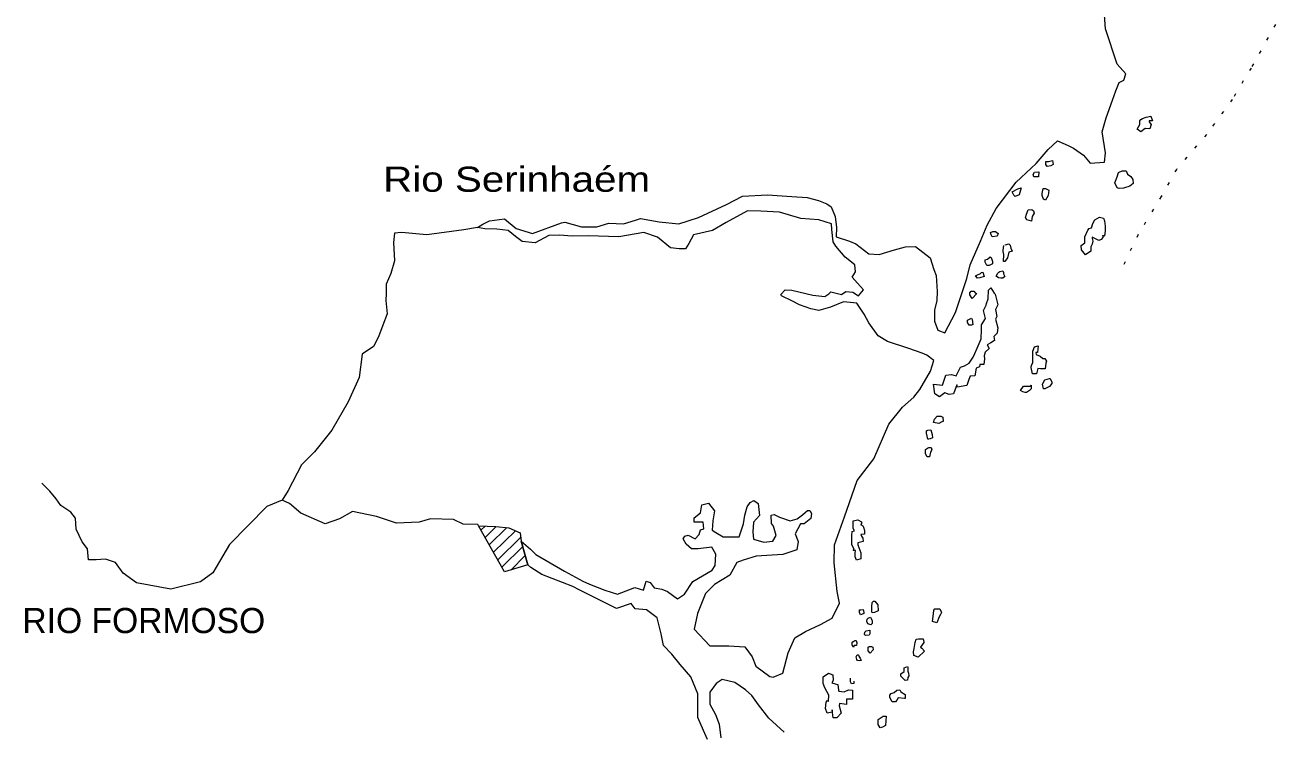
# Model space of a CAD drawing. Extents: x 47169 to 972804, y 7447977 to 9608469.
# Drawn here: x 910159 to 944005, y 9035587 to 9054600 of the extents above; entities that cross this region are included whole.
import ezdxf
from ezdxf.enums import TextEntityAlignment as Align

# ---------------------------------------------------------------- set-up
doc = ezdxf.new("R2010")
doc.units = 0
doc.header["$LTSCALE"] = 270
doc.linetypes.add('DOTTED', pattern=[1.5, 0.3, -1.2])
doc.layers.add('1', color=7, linetype='Continuous', lineweight=13)
doc.layers.add('3', color=7, linetype='Continuous')

msp = doc.modelspace()

# ---------------------------------------------------------------- linework, layer by layer
at = {"layer": '1'}
for p, q in [((922423.9, 9041014.5), (922536.4, 9041125.3)), ((922536.6, 9040816.1), (922837.3, 9041111.2)), ((922650.4, 9040616.6), (923122.6, 9041082.8)), ((922763.1, 9040418.3), (923351.1, 9040996.3)), ((922876.8, 9040218.8), (923493.9, 9040827.5)), ((922989.5, 9040020.4), (923548.6, 9040571)), ((923224.7, 9039941.6), (923616.7, 9040327.6)), ((923675.9, 9040075.5), (923684.8, 9040085.4))]:
    msp.add_line(p, q, dxfattribs=at)
at = {"layer": '1', "linetype": 'DOTTED'}
msp.add_lwpolyline([(944005.3, 9054971), (943148.7, 9053447.1), (942644.5, 9052604.6), (941948.4, 9051658.7), (941141, 9050720.6), (940731.9, 9049991.2), (940107.8, 9048964.8), (939666.9, 9048042.9)], dxfattribs=at)
at = {"layer": '1'}
for points in [[(938224.3, 9051360.5), (938367, 9051287), (938636.4, 9051099.1), (938818.4, 9050888.9), (939201.5, 9050917), (939228.3, 9051165), (939146, 9051734.4), (939253.6, 9052109), (939418.4, 9052579.4), (939508.2, 9052834.5), (939598.8, 9053057.4), (939727.4, 9053120.3), (939784.3, 9053287.1), (939547.6, 9053546.7), (939229.8, 9054502), (939209.4, 9054871.2)], [(930608.6, 9047475.9), (930791.6, 9047474), (931357.1, 9047331.9), (931676.6, 9047296.5), (931788.8, 9047375.2), (931837.8, 9047422.3), (932123.9, 9047355.1), (932244.9, 9047433.7), (932435.6, 9047416.2), (932586.8, 9047318.2), (932716.3, 9047476.5), (932558.2, 9047654.3), (932416.6, 9047824.2), (932505.2, 9047967.3), (932482.8, 9048151.5), (932222.5, 9048362.5), (931977.3, 9048653.2), (931906.8, 9048774.7), (931870.5, 9049103.1), (931855.5, 9049255.1), (931513.5, 9049362.7), (931035.2, 9049400.8), (930461.1, 9049567.4), (929958.5, 9049596.9), (929600, 9049600.5), (929022.3, 9049295), (928660.5, 9049074.8), (928148.6, 9048960.4), (928018.3, 9048730.1), (927928.6, 9048579.2), (927760.9, 9048580.9), (927521.9, 9048607.7), (927174.1, 9048899.3), (926808.1, 9049023.8), (926136.2, 9048903.2), (925857.3, 9048913.7), (925322.5, 9048928), (924882.4, 9048924.7), (924539.7, 9048952.5), (924252.8, 9048939.9), (923883.6, 9048744.1), (923532.1, 9048779.8), (923358.1, 9048917.8), (923160, 9049071.6), (922849.5, 9049115.7), (922529.7, 9049118.9), (922330.4, 9049153.1), (922475.8, 9049248), (922652, 9049333.8), (923059.5, 9049385.1), (923375.7, 9049133.7), (923814.4, 9048993), (924591.5, 9049280), (924686.6, 9049303.4), (925133.1, 9049170.4), (925540.1, 9049174), (925868.7, 9049273.8), (926258.9, 9049253.2), (926587.5, 9049354), (926715.9, 9049400.4), (927217.9, 9049306.7), (927752.3, 9049253.6), (928280.2, 9049423.3), (929034.8, 9049774.7), (929459.6, 9050002), (930139.4, 9050035), (930793, 9049987.3), (931199.8, 9049966.6), (931510, 9049883.6), (931733, 9049792.7), (931852.4, 9049711.7), (931953.5, 9049454.6), (931990.1, 9049157.3), (931987.6, 9048909.1), (932345.9, 9048785.7), (932512.9, 9048719.7), (932862, 9048451.3), (933140.9, 9048431.8), (933556.9, 9048556.1), (933853.4, 9048640.6), (934117, 9048645.6), (934513.2, 9048344.6), (934613.6, 9048023.2), (934675.9, 9047863), (934703.6, 9047438.3), (934693.3, 9047190.2), (934634.4, 9046934.8), (934631.3, 9046638.9), (934717, 9046389.8), (934908.2, 9046323.5), (935193, 9046872.5), (935498, 9047781.4), (935588.9, 9048148.4), (935866.8, 9048786.1), (936046.7, 9049216.4), (936290.7, 9049669.4), (936833, 9050375.2), (937364.3, 9050874), (937688.2, 9051254.1), (937937.7, 9051492), (938224.3, 9051360.5)], [(937700.3, 9050933.7), (937804.2, 9050957), (937827.4, 9050852.6), (937763, 9050813.4), (937666.9, 9050797.7), (937627.7, 9050846.9), (937628.3, 9050902.3), (937628.6, 9050934.4), (937692.6, 9050933.8)], [(922330.4, 9049153.1), (921962.5, 9049093.6), (920971.9, 9048960.5), (920285.4, 9049023.9), (920102.1, 9049001.3), (920075.4, 9048753.4), (920094.7, 9048257.9), (920004.2, 9047922), (919873.5, 9047635.2), (919870.9, 9047379.3), (919869.1, 9047195.3), (919905.2, 9046834.9), (919783.1, 9046532.5), (919668.5, 9046213.4), (919530.2, 9045951.1), (919224.9, 9045745.8), (919147, 9045122.8), (918852.7, 9044469.8), (918415, 9043706.3), (917946.1, 9043119.2), (917599.7, 9042771.5), (917233.3, 9042079.3), (917079.7, 9041824.9)], [(936528.8, 9048690.6), (936632.7, 9048712.8), (936664.3, 9048680.3), (936687.8, 9048600.2), (936717.8, 9048520.2), (936630.4, 9048488.9), (936596.8, 9048337.4), (936524.1, 9048241.8), (936492.1, 9048242.1), (936494.1, 9048426.1), (936478.4, 9048514.9), (936478.7, 9048547), (936496.6, 9048674.3)], [(928004.5, 9040879.1), (928186.6, 9040780.8), (928300.3, 9040899.4), (928333.5, 9041018.7), (928420.9, 9041049.9), (928407.3, 9041226.3), (928159.2, 9041228.8), (928160.4, 9041349.6), (928329.3, 9041475.3), (928371.3, 9041698.7), (928548.2, 9041736.8), (928706, 9041535.7), (928662.4, 9041263.6), (928644.4, 9041015.5), (928747.4, 9040950.2), (928945.9, 9040836.2), (929145.4, 9040834.2), (929377, 9040831.8), (929492, 9041181.9), (929526.3, 9041414.3), (929592.6, 9041637.5), (929673.2, 9041756.3), (929769.7, 9041811.8), (929889.1, 9041729.7), (929917.8, 9041409.2), (929763.7, 9041226.8), (929737.9, 9040971.1), (929759, 9040771.4), (930038.3, 9040687.6), (930277.9, 9040717.3), (930366.6, 9040868.2), (930297.4, 9041117.1), (930243, 9041189.7), (930236.5, 9041413.6), (930317.3, 9041437.2), (930459.9, 9041363.7), (930746.7, 9041264.3), (930938, 9041317.8), (931082.5, 9041428.2), (931147.1, 9041491.8), (931211.6, 9041538.8), (931275.6, 9041538.2), (931323.2, 9041457.9), (931305.4, 9041329.5), (931120.8, 9041179.6), (931024.8, 9041180.6), (930878.7, 9040910.6), (930963.7, 9040709.1), (930929.4, 9040485.6), (930545.4, 9040354.4), (929827.1, 9040314.1), (929482, 9040205.8), (929313.7, 9040144.3), (929127.1, 9039801.6), (928709.9, 9039549.9), (928468.1, 9039305.3), (928255.3, 9038771.1), (928162.8, 9038347.6), (928581.6, 9037903.4), (929099.8, 9037897), (929523, 9037876), (929719.8, 9037602.5), (929820.9, 9037353.2), (930201.8, 9037076.7), (930288.7, 9037059.1), (930545.7, 9037168.4), (930694.6, 9037711), (930874.1, 9038116.9), (931154.9, 9038290.2), (931563.8, 9038477.7), (931877.5, 9038641.8), (932072.5, 9039047.6), (932011.8, 9039360.7), (931932.6, 9040130.6), (931936.6, 9040618.2), (932207.9, 9041367.8), (932545.5, 9042348.4), (932998.3, 9042935.5), (933398.3, 9043866.7), (933770.2, 9044319.5), (934076.4, 9044595.6), (934238.4, 9044802.2), (934522.5, 9045286.9), (934612.6, 9045574.1), (934423.3, 9045720.1), (934296, 9045778), (933937.7, 9045902.5), (933365, 9046092.3), (933118.3, 9046240), (932859.5, 9046595.1), (932741.6, 9046820.2), (932537.3, 9047118.1), (932178.1, 9047155.1), (931833.6, 9047014.6), (931520.5, 9046921.3), (931298.3, 9046972.4), (930996, 9047071.9), (930812.8, 9047170.2), (930511, 9047317.3), (930495.9, 9047349.6), (930608.6, 9047475.9)], [(922355.7, 9041133.8), (922340.6, 9041166), (921949.2, 9041178.9), (921686.9, 9041301.2), (921065.2, 9041316.3), (920761, 9041224.1), (920154.2, 9041198), (919613.6, 9041380.7), (918967.7, 9041515.7), (918615.1, 9041319.8), (918230, 9041187.4), (917578.9, 9041466.4), (917269.5, 9041734.3), (917079.7, 9041824.9), (916662.3, 9041652.8), (915655.3, 9040623.6), (915208.9, 9039867.9), (914879.1, 9039624.1), (914079.9, 9039424.8), (913155.5, 9039594.7), (912798.6, 9039855.2), (912594.2, 9040145.3), (912323.9, 9040235.5), (912067.9, 9040214.8), (911860.6, 9040216.8), (911839.3, 9040512.8), (911690.1, 9040699.3), (911533.6, 9041044.3), (911512.2, 9041332.6), (911385.8, 9041494.5), (911116.5, 9041681.1), (910990.3, 9041858.5), (910824.7, 9042060.6), (910611.8, 9042278.8)], [(928524.8, 9035383), (928414.8, 9035623.5), (928258.5, 9035969.7), (928261.5, 9036257.8), (928265.1, 9036610.1), (928070.2, 9037068.7), (927785.8, 9037399.6), (927565.9, 9037674.5), (927336.8, 9037909.5), (927276, 9038221.5), (927168, 9038654.8), (926883.4, 9038866), (926571.7, 9038893.6), (926469.5, 9039039.8), (926069, 9038907.6), (925068.4, 9039407.6), (924894, 9039496.9), (924067, 9039818.9), (923765.6, 9040005.9), (923687, 9040078.7), (923509.2, 9040713.2), (923755.2, 9040502.4), (923904.8, 9040356.8), (924674.3, 9039908), (925166.7, 9039638.2), (925350.1, 9039564.3), (925755.3, 9039399.5), (926097.2, 9039291.8), (926569.8, 9039469.8), (926800.6, 9039395.5), (926874.8, 9039642.9), (926978.1, 9039602), (927088, 9039464.5), (927296, 9039422.5), (927446.5, 9039364.5), (927581.1, 9039266.7), (927715.8, 9039168.9), (927901.2, 9039295.5), (928127.4, 9039629), (928649.9, 9039935), (928730.6, 9040062.8), (928750.3, 9040366.2), (928639.8, 9040559), (928272, 9040507.4), (928089, 9040509.2), (927945.8, 9040639.3), (927867.8, 9040776.3), (927908.3, 9040848), (928004.5, 9040879.1)], [(932458.8, 9036954.7), (932458.2, 9036890.4), (932394.1, 9036875.6), (932370.4, 9036931.2), (932370.7, 9036963.3), (932371.4, 9037027.6)], [(930585.4, 9035575.6), (930173.7, 9035956.6), (929898.4, 9036311.8), (929716.8, 9036561.9), (929543.1, 9036715.5), (929258.4, 9036911.3), (928915.2, 9036994.6), (928755.3, 9036884.3), (928585.3, 9036654.5), (928582, 9036334.3), (928739, 9036052.3), (928832.3, 9035795.3), (928883.6, 9035426.9)]]:
    msp.add_lwpolyline(points, dxfattribs=at)
for points in [[(940227.5, 9052090), (940323.8, 9052121.1), (940452.1, 9052150.8), (940498.2, 9052022.9), (940411.1, 9052023.8), (940410.8, 9051999.4), (940457.5, 9051926.9), (940424.3, 9051815.3), (940296.4, 9051816.7), (940184.1, 9051730.3), (940081.1, 9051803.4), (940154.2, 9051930.1), (940155.2, 9052026.5), (940187.6, 9052066)], [(937442.6, 9050657.1), (937433.5, 9050520.9), (937369.5, 9050521.5), (937305.6, 9050522.2), (937289.7, 9050586.6), (937322.2, 9050641.7)], [(939721.5, 9050214.5), (939601.2, 9050208), (939546.2, 9050224.1), (939483.7, 9050361.1), (939549.3, 9050521.1), (939582.5, 9050632.7), (939677.8, 9050679.3), (939790.3, 9050678.2), (939821.4, 9050589.2), (939916.7, 9050525), (939971.1, 9050451.3), (939978.8, 9050339.3), (939889.8, 9050268.2)], [(936870.9, 9050198.7), (936967.1, 9050222), (936908.9, 9050030.9), (936804.8, 9049992.1), (936765.4, 9050024.6), (936718.9, 9050120.4)], [(937692, 9050021.7), (937618.9, 9049893.9), (937562.9, 9049918.9), (937524.2, 9050015.7), (937524.8, 9050071.1), (937558.2, 9050207.1), (937621.1, 9050206.4), (937708.8, 9050157.8)], [(937311.9, 9049538), (937262.5, 9049449.9), (937236.9, 9049322.7), (937118.2, 9049363.8), (937079.1, 9049428.5), (937103.2, 9049515.8), (937153, 9049636.1), (937249, 9049642.8), (937296, 9049601.3)], [(938878.2, 9048895.6), (938877.9, 9048863.5), (938892.6, 9048791.3), (938876.3, 9048711.7), (938835.9, 9048640), (938834.6, 9048519.2), (938697.9, 9048417.6), (938586.8, 9048555.1), (938580.3, 9048674.8), (938677, 9048745.9), (938678.7, 9048905.4), (938759.9, 9049080.8), (938792.4, 9049128.1), (938856.6, 9049144.1), (938889.8, 9049263.4), (938946, 9049359.2), (939067, 9049437.8), (939178.1, 9049404.5), (939209.3, 9049332.1), (939224.4, 9049187.9), (939223.4, 9049091.5), (939223, 9049059.4), (939205.2, 9048932.1), (939173, 9048915.8), (939157.9, 9048948.1), (939157.2, 9048883.8), (939117, 9048836.6), (939052.7, 9048805.1)], [(936347.7, 9048996.1), (936315, 9048924.4), (936186.8, 9048902.4), (936155.4, 9048958.2), (936140.6, 9049022.6), (936204.8, 9049046.3), (936268.8, 9049045.7)], [(936157.9, 9048349.7), (936188.8, 9048245.2), (936195.9, 9048182), (936099.4, 9048134.2), (936035.5, 9048134.9), (935996.7, 9048224), (935997.3, 9048288.2), (936061.5, 9048303.1), (936126.1, 9048366.7)], [(935969.5, 9047839.7), (935848.9, 9047801), (935784.9, 9047793.9), (935738.1, 9047858.7), (935770.2, 9047873.9), (935865.6, 9047921.7), (935897.8, 9047944.6), (935929.9, 9047952)], [(936361.2, 9047955.3), (936393.4, 9047971.6), (936472.9, 9047986.3), (936489.1, 9047946.2), (936488.8, 9047914.1), (936519.9, 9047834), (936472.1, 9047794.6), (936415.8, 9047795.2), (936351.9, 9047803.6), (936288.4, 9047844.1), (936336.6, 9047923.4)], [(936046.5, 9045998.1), (936101.7, 9045901.1), (935995.8, 9045799.2), (935964, 9045703.1), (935978.6, 9045623.1), (935961.6, 9045471.5), (935849.1, 9045472.7), (935840.7, 9045408.5), (935752.1, 9045369.5), (935719, 9045161.5), (935591, 9045155), (935558.1, 9045067.8), (935500.2, 9044907.8), (935252.7, 9044862.7), (935229.1, 9044927.2), (935139.4, 9044679.9), (935026.7, 9044665.5), (934908.1, 9044706.7), (934762.4, 9044596.2), (934636.5, 9044685.1), (934607.2, 9044942.5), (934846.2, 9044915.6), (934936.2, 9045186.2), (935088.5, 9045201.2), (935216.1, 9045167.8), (935329.9, 9045398.2), (935441.7, 9045437), (935562.7, 9045507.8), (935668, 9045666.2), (935716.4, 9045762.2), (935782, 9045913.3), (935830.6, 9046032.5), (935888.2, 9046160.5), (935898.6, 9046416.3), (935899.8, 9046536), (936005.3, 9046711.1), (935952.3, 9046920), (936016.7, 9047063.4), (936026, 9047111), (936074.7, 9047239), (936084.9, 9047470.6), (936149.5, 9047534.2), (936236.2, 9047389.2), (936259.1, 9047364.6), (936336.7, 9047075.6), (936271.4, 9046947.8), (936309.2, 9046763.4), (936268.7, 9046691.8), (936338, 9046459.4), (936329.6, 9046395.3), (936313.3, 9046315.6), (936231.9, 9046227.8), (936247.3, 9046115.7), (936143, 9046053.6)], [(935772.8, 9047378.5), (935643.5, 9047243.5), (935580.5, 9047340.6), (935581.1, 9047396), (935621.3, 9047444.3), (935653.3, 9047442.9), (935685.3, 9047442.6), (935733.2, 9047386.6)], [(935630.3, 9046715), (935646.5, 9046682.7), (935660.6, 9046547.4), (935628.4, 9046531.1), (935564.5, 9046531.7), (935517.7, 9046596.5), (935518.3, 9046660.8)], [(937543.8, 9045629), (937599, 9045636.2), (937646.8, 9045563.7), (937629.7, 9045508.5), (937604.9, 9045355.8), (937484.7, 9045357), (937413, 9045358.9), (937371.8, 9045215.2), (937268.2, 9045216.3), (937229.2, 9045392.9), (937238.7, 9045456), (937279, 9045512.1), (937273, 9045680.6), (937274.6, 9045832.4), (937323.2, 9045943.9), (937419.4, 9045975), (937401, 9045791.2), (937353.6, 9045791.7), (937368.4, 9045735.1), (937472.8, 9045694.1)], [(937025.3, 9044883.1), (937121.4, 9044889.8), (937200.8, 9044889), (937233, 9044911.9), (937232, 9044816.6), (937183, 9044768.4), (937103, 9044713.8), (937071, 9044714.1), (937007.3, 9044739.2), (936943.7, 9044770.9)], [(937727.9, 9044882.4), (937599.2, 9044811.7), (937567.3, 9044812), (937536.6, 9044940.9), (937601.8, 9045059.9), (937721.3, 9045090.8), (937745.5, 9045090.6), (937792, 9044993.7), (937791.6, 9044961.5)], [(934828.3, 9043930.6), (934747.3, 9043883.8), (934604.2, 9043909.7), (934629.4, 9043997), (934702, 9044084.8), (934734, 9044084.5), (934797.9, 9044083.8), (934852.7, 9044051.2), (934860.4, 9043939.1)], [(934480.5, 9043463.2), (934448.5, 9043463.6), (934418.2, 9043623.5), (934418.8, 9043687.7), (934451, 9043702.9), (934530.5, 9043709.8), (934568.9, 9043589.8), (934575.6, 9043493.3), (934512.5, 9043470.7)], [(934524.2, 9043110.4), (934498.7, 9042982.1), (934435.8, 9042982.7), (934388.1, 9043064.1), (934389.3, 9043183.8), (934446, 9043223.1), (934478.1, 9043238.3), (934542.1, 9043237.6), (934556.9, 9043174.3)], [(923687, 9040078.7), (923062.1, 9039893.3), (922355.7, 9041133.8), (922826.3, 9041112.4), (923177.7, 9041076.7), (923479.5, 9040937.3), (923509.2, 9040713.2)], [(932470.2, 9040500.8), (932407.5, 9040621.1), (932410.1, 9040869.3), (932411.1, 9040973.5), (932475.3, 9040996.1), (932444, 9041060.7), (932438.4, 9041261.3), (932566.6, 9041291), (932669.7, 9041234.5), (932669.1, 9041178), (932637, 9041162.8), (932700.6, 9041130), (932715.7, 9041097.8), (932746.7, 9041001), (932745.7, 9040905.7), (932649.7, 9040897.8), (932665.7, 9040850), (932704.8, 9040794.2), (932711.6, 9040705.5), (932567.9, 9040674.8), (932567.4, 9040619.4), (932645.6, 9040402.5), (932644, 9040241.8), (932531.1, 9040203.1), (932492.4, 9040299.9), (932493.4, 9040396.3), (932501.8, 9040468.3), (932437.9, 9040469)], [(932941.6, 9038949.9), (932957.1, 9039068.4), (932991.7, 9039101.2), (933023.6, 9039100.9), (933102, 9039004.8), (933116.9, 9038844), (933020.5, 9038797.3), (932956.5, 9038790.2), (932940.3, 9038822.5), (932940.9, 9038885.7)], [(932668.2, 9038745.6), (932636.1, 9038737), (932613.6, 9038801.5), (932614.3, 9038865.8), (932645.2, 9038873.2), (932709.3, 9038880.3), (932725, 9038800.4), (932724.7, 9038768.2)], [(934608.1, 9038763.1), (934609.1, 9038859.5), (934641.5, 9038899), (934777.2, 9038897.6), (934823.6, 9038800.7), (934792.1, 9038744.5), (934759.5, 9038681.7), (934693.8, 9038521.7), (934574, 9038555.1)], [(932810.7, 9038559), (932815.7, 9038614.4), (932845.8, 9038649.5), (932906.7, 9038669.9), (932922.9, 9038637.6), (932954.2, 9038574.1), (932953.5, 9038502.1), (932921.1, 9038462.6), (932833.2, 9038495.6)], [(932887.6, 9038318.8), (932886.6, 9038222.4), (932870.8, 9038190.5), (932774.8, 9038183.7), (932750.8, 9038208.3), (932751.5, 9038271.5), (932791.5, 9038303.2)], [(934255.8, 9037862.4), (934287.5, 9037837.7), (934358.4, 9037757.2), (934189.1, 9037599.4), (934078.2, 9037640.4), (934062.6, 9037737), (934080.2, 9037832.1), (934106.1, 9037992.6), (934137.9, 9038079.8), (934201.9, 9038086.9), (934265.8, 9038086.2), (934329.8, 9038085.5), (934337.2, 9038053.3), (934345.3, 9037990.1)], [(932461.1, 9038027.4), (932493.3, 9038042.6), (932525.2, 9038042.2), (932541.1, 9037977.8), (932532.8, 9037914.7), (932500.7, 9037906.2), (932468.7, 9037906.5), (932444, 9037866.9), (932412.7, 9037931.5), (932413.4, 9037995.7)], [(932897.8, 9037702.6), (932849.9, 9037766.2), (932843.2, 9037862.7), (932875.4, 9037886.8), (932939.4, 9037886.1), (932971.1, 9037861.4), (932978.1, 9037797)], [(932632.8, 9037569), (932656.4, 9037504.5), (932624.3, 9037497.1), (932560.5, 9037505.5), (932536.6, 9037537.9), (932520.7, 9037602.3), (932553.2, 9037657.4), (932585.2, 9037657.1), (932593.7, 9037625.9)], [(931774.9, 9036402.1), (931784.4, 9036570.5), (931682.8, 9036771), (931636.6, 9036884.5), (931637.4, 9037068.5), (931774, 9037162.3), (931893.8, 9037121.2), (931899.9, 9036969.3), (931867.3, 9036905.4), (931955.2, 9036880.1), (932026.7, 9036863.8), (932049.4, 9036710.7), (932056.8, 9036679.6), (932200, 9036661.5), (932320.7, 9036715.6), (932424.3, 9036706.8), (932421.8, 9036466.3), (932261.9, 9036469.1), (932261.1, 9036388.2), (932260.4, 9036325.1), (932077.7, 9036350.2), (932069.3, 9036287.1), (932114.6, 9036086.1), (932002, 9035967.6), (931906.1, 9035968.6), (931876.3, 9036177.2), (931875.6, 9036113), (931739.7, 9036090), (931701.3, 9036211.2), (931718.6, 9036387.2), (931751, 9036426.8)], [(933810.1, 9037211), (933818.8, 9037307.3), (933899.8, 9037346.4), (933914.8, 9037314.1), (933913.8, 9037217.7), (933929.8, 9037162.1), (933936.9, 9037097.8), (933912.1, 9037050.4), (933903.6, 9036978.4), (933839.6, 9036971.3), (933721.7, 9037084.5), (933722.4, 9037148.8)], [(933651.7, 9036501.2), (933619, 9036437.3), (933578.9, 9036397.8), (933490.7, 9036398.7), (933427.9, 9036511.3), (933428.6, 9036575.6), (933468.7, 9036615), (933549.5, 9036646.3), (933614.1, 9036708.8), (933693.6, 9036716.9), (933725, 9036660), (933843.4, 9036594.5), (933843.3, 9036482.6), (933819.1, 9036482.8)], [(933247.4, 9036008.9), (933326.7, 9036008.1), (933316.5, 9035760), (933228.8, 9035713.2), (933164.7, 9035698.4), (933117.1, 9035786.4), (933118.5, 9035915)]]:
    msp.add_lwpolyline(points, close=True, dxfattribs=at)

# ---------------------------------------------------------------- texts
at = {"layer": '3', "width": 1.2}
msp.add_text('Rio Serinhaém', height=676.9, dxfattribs=at).set_placement((926977.4, 9050117.1), align=Align.RIGHT)
at = {"layer": '3'}
msp.add_text('RIO FORMOSO', height=676.7, dxfattribs=at).set_placement((916619.9, 9038243.4), align=Align.RIGHT)

doc.saveas('drawing.dxf')
